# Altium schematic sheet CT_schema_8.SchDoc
size 251 x 159 mm
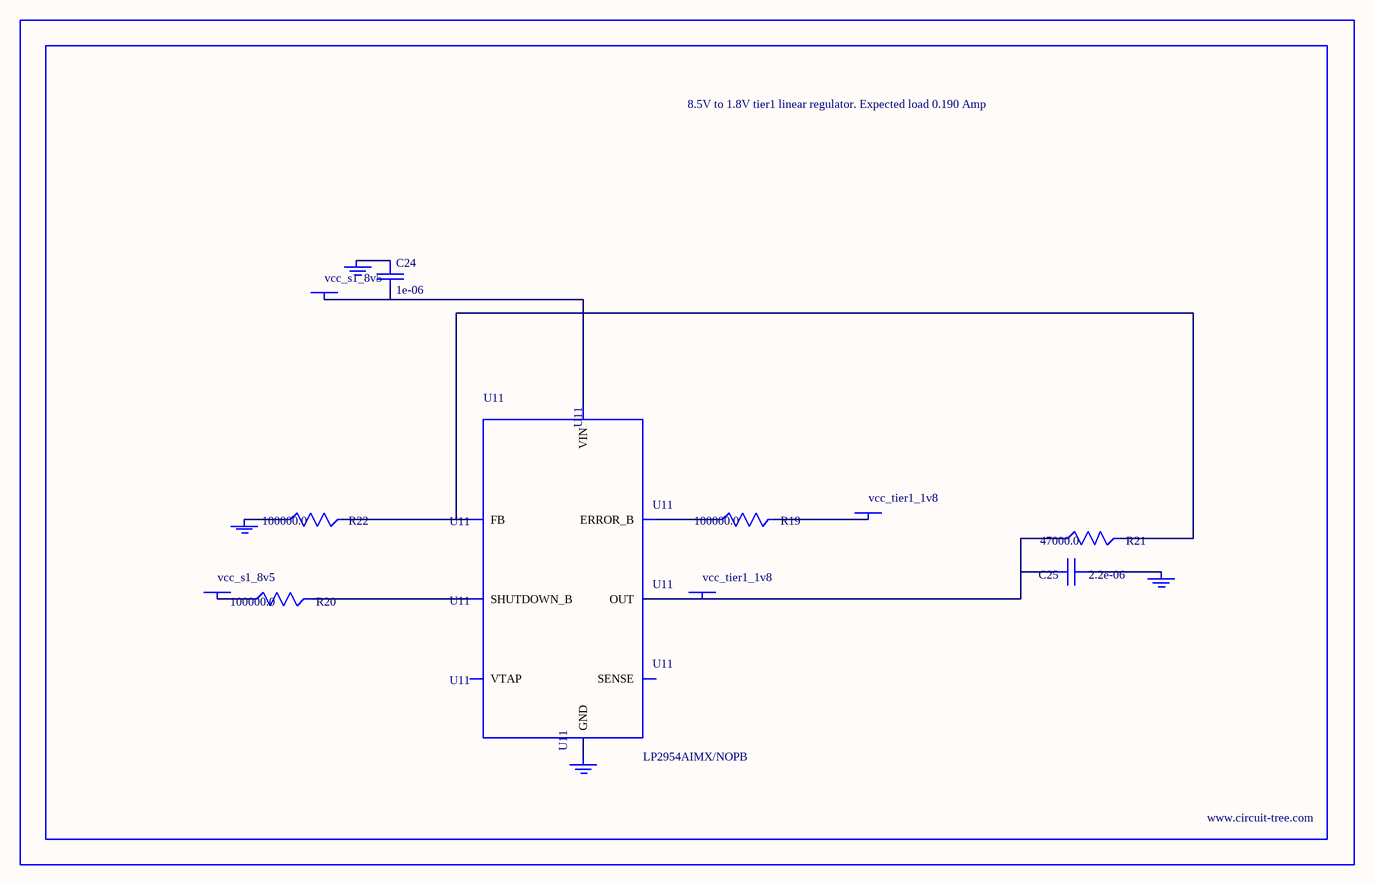
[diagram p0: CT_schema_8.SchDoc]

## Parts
BORDER7  (no value)
C24  1e-06  [EXV-9B]
C25  2.2e-06  [EXV-9B]
GND_INSTANCE_7_0  (no value)
GND_INSTANCE_7_1  (no value)
GND_INSTANCE_7_2  (no value)
GND_INSTANCE_7_3  (no value)
POWER_INSTANCE_7_0  vcc_s1_8v5
POWER_INSTANCE_7_1  vcc_tier1_1v8
POWER_INSTANCE_7_2  vcc_s1_8v5
POWER_INSTANCE_7_3  vcc_tier1_1v8
R19  100000.0  [R0603]
R20  100000.0  [R0603]
R21  47000.0  [R0603]
R22  100000.0  [R0603]
U11  LP2954AIMX/NOPB  [LP2954]

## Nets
NetC24_1: C24.1 GND_INSTANCE_7_2.0(GND)
NetC24_2: C24.2 POWER_INSTANCE_7_2.0(PWR) U11.8(VIN)
NetC25_1: C25.1 GND_INSTANCE_7_0.0(GND)
NetC25_2: C25.2 POWER_INSTANCE_7_3.0(PWR) R21.1 U11.1(OUT)
NetGND_INSTANCE_7_1_0: GND_INSTANCE_7_1.0(GND) R22.1
NetGND_INSTANCE_7_3_0: GND_INSTANCE_7_3.0(GND) U11.4(GND)
NetPOWER_INSTANCE_7_0_0: POWER_INSTANCE_7_0.0(PWR) R20.1
NetPOWER_INSTANCE_7_1_0: POWER_INSTANCE_7_1.0(PWR) R19.2
NetR19_1: R19.1 U11.5(ERROR_B)
NetR20_2: R20.2 U11.3(SHUTDOWN_B)
NetR21_2: R21.2 R22.2 U11.7(FB)

Not connected (* = marked no-connect by the designer): U11 2(SENSE) 6(VTAP)

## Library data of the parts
BORDER7 = BORDER_PAGE7
C24 = EDK105M050A9BAA
C25 = EDK225M050A9BAA
GND_INSTANCE_7_0-GND_INSTANCE_7_3 = GND
POWER_INSTANCE_7_0-POWER_INSTANCE_7_3 = PWR
R19 R20 R22 = RC0603JR-07100KL
R21 = RC0603JR-0747KL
